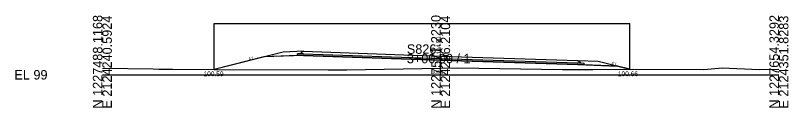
# Model space of a CAD drawing. Extents: x 2118382 to 2118616, y 1213030 to 1222057.
# Drawn here: x 2118381.9 to 2118610.4, y 1213530.1 to 1213557.3 of the extents above; entities that cross this region are included whole.
import ezdxf

# ---------------------------------------------------------------- set-up
doc = ezdxf.new("R2010")
doc.units = 0
for name, color, linetype in [('XS_CELL', 7, 'Continuous'), ('XS_M_DITCH', 7, 'Continuous'), ('XS_M_SHAPES_EARTHWORK', 7, 'Continuous'), ('XS_P_FINISHED_GRADE', 7, 'Continuous'), ('XS_P_FINISHED_GRADE_ELEV_TX', 7, 'Continuous'), ('XS_P_SUBGRADE_GRANULAR', 7, 'Continuous'), ('XS_P_SUBGRADE_PAVEMENT', 7, 'Continuous'), ('XS_P_TX_DCH', 7, 'Continuous'), ('XS_P_TX_FS_BS', 7, 'Continuous'), ('XS_X_GROUND', 7, 'Continuous'), ('XS_X_GROUND_TX', 7, 'Continuous')]:
    doc.layers.add(name, color=color, linetype=linetype)

msp = doc.modelspace()

# ---------------------------------------------------------------- linework, layer by layer
at = {"layer": 'XS_CELL'}
for p, q in [((2118507.6, 1213539.8), (2118507.6, 1213546)), ((2118407.6, 1213539.8), (2118507.6, 1213539.8)), ((2118507.6, 1213539.8), (2118607.6, 1213539.8))]:
    msp.add_line(p, q, dxfattribs=at)
at = {"layer": 'XS_M_DITCH'}
for p, q in [((2118440.64, 1213541.39), (2118440.64, 1213554.96)), ((2118440.64, 1213554.96), (2118563.5, 1213554.96)), ((2118563.5, 1213541.46), (2118563.5, 1213554.96))]:
    msp.add_line(p, q, dxfattribs=at)
at = {"layer": 'XS_M_SHAPES_EARTHWORK'}
for p, q in [((2118455.33, 1213545.07), (2118440.64, 1213541.39)), ((2118507.56, 1213544.09), (2118467.08, 1213545.54)), ((2118548.16, 1213542.83), (2118507.56, 1213544.09)), ((2118550.01, 1213542.75), (2118548.16, 1213542.83)), ((2118559.92, 1213542.36), (2118550.01, 1213542.75)), ((2118550.01, 1213542.75), (2118550.01, 1213542.75)), ((2118440.64, 1213541.39), (2118441.67, 1213541.39)), ((2118441.67, 1213541.39), (2118474.37, 1213541.22)), ((2118474.37, 1213541.22), (2118479.89, 1213541.24)), ((2118479.89, 1213541.24), (2118507.6, 1213541.77)), ((2118507.6, 1213541.77), (2118512.72, 1213541.87)), ((2118512.72, 1213541.87), (2118543.67, 1213541.39)), ((2118543.67, 1213541.39), (2118552.55, 1213541.39)), ((2118552.55, 1213541.39), (2118563.5, 1213541.46)), ((2118563.5, 1213541.46), (2118559.92, 1213542.36))]:
    msp.add_line(p, q, dxfattribs=at)
for points in [[(2118467.08, 1213545.54), (2118465.24, 1213545.46), (2118455.33, 1213545.07)], [(2118550.01, 1213542.75), (2118550.01, 1213542.75)]]:
    msp.add_lwpolyline(points, dxfattribs=at)
at = {"layer": 'XS_P_FINISHED_GRADE'}
for p, q in [((2118461.08, 1213546.5), (2118440.64, 1213541.39)), ((2118467.08, 1213546.74), (2118461.08, 1213546.5)), ((2118467.08, 1213546.74), (2118507.6, 1213545.3)), ((2118507.6, 1213545.3), (2118548.16, 1213544.04)), ((2118548.16, 1213544.04), (2118554.16, 1213543.8)), ((2118554.16, 1213543.8), (2118563.5, 1213541.46))]:
    msp.add_line(p, q, dxfattribs=at)
at = {"layer": 'XS_P_SUBGRADE_GRANULAR'}
for p, q in [((2118467.08, 1213545.54), (2118455.33, 1213545.07)), ((2118466.24, 1213546), (2118465.24, 1213545.96)), ((2118465.24, 1213545.46), (2118465.24, 1213545.96)), ((2118467.08, 1213545.54), (2118507.56, 1213544.09)), ((2118507.56, 1213544.09), (2118548.16, 1213542.83)), ((2118548.16, 1213542.83), (2118559.92, 1213542.36)), ((2118549.01, 1213543.29), (2118550.01, 1213543.25)), ((2118550.01, 1213542.75), (2118550.01, 1213543.25))]:
    msp.add_line(p, q, dxfattribs=at)
at = {"layer": 'XS_P_SUBGRADE_PAVEMENT'}
for p, q in [((2118466.39, 1213546.26), (2118466.24, 1213546)), ((2118467.08, 1213546.04), (2118466.24, 1213546)), ((2118467.08, 1213546.74), (2118466.39, 1213546.26)), ((2118467.08, 1213546.04), (2118507.58, 1213544.59)), ((2118507.58, 1213544.59), (2118548.16, 1213543.33)), ((2118548.16, 1213544.04), (2118548.86, 1213543.55)), ((2118548.16, 1213543.33), (2118549.01, 1213543.29)), ((2118548.86, 1213543.55), (2118549.01, 1213543.29))]:
    msp.add_line(p, q, dxfattribs=at)
at = {"layer": 'XS_X_GROUND'}
for p, q in [((2118407.6, 1213541.76), (2118422.59, 1213541.56)), ((2118422.59, 1213541.56), (2118424.3, 1213541.42)), ((2118424.3, 1213541.42), (2118428.37, 1213541.43)), ((2118428.37, 1213541.43), (2118441.67, 1213541.39)), ((2118441.67, 1213541.39), (2118474.37, 1213541.22)), ((2118474.37, 1213541.22), (2118479.89, 1213541.24)), ((2118479.89, 1213541.24), (2118507.6, 1213541.77)), ((2118507.6, 1213541.77), (2118512.72, 1213541.87)), ((2118512.72, 1213541.87), (2118543.67, 1213541.39)), ((2118543.67, 1213541.39), (2118552.55, 1213541.39)), ((2118552.55, 1213541.39), (2118564.69, 1213541.47)), ((2118564.69, 1213541.47), (2118585.36, 1213541.37)), ((2118585.36, 1213541.37), (2118590.78, 1213541.82)), ((2118590.78, 1213541.82), (2118601.73, 1213541.33)), ((2118601.73, 1213541.33), (2118607.6, 1213541.43))]:
    msp.add_line(p, q, dxfattribs=at)

# ---------------------------------------------------------------- texts
at = {"layer": 'XS_CELL'}
for s, p in [('N 1227488.1168', (2118407.6, 1213529.8)), ('E 2124240.5924', (2118410.4, 1213529.8)), ('N 1227571.2230', (2118507.6, 1213529.8)), ('E 2124296.2104', (2118510.4, 1213529.8)), ('N 1227654.3292', (2118607.6, 1213529.8)), ('E 2124351.8283', (2118610.4, 1213529.8))]:
    msp.add_text(s, height=2.8, rotation=90, dxfattribs=at).set_placement(p)
for s, p in [('S826', (2118497.6, 1213546)), ('3+00.00 / 1', (2118497.6, 1213543.2)), ('EL 99', (2118381.6, 1213538.4))]:
    msp.add_text(s, height=2.8, dxfattribs=at).set_placement(p)
at = {"layer": 'XS_P_FINISHED_GRADE_ELEV_TX'}
msp.add_text(' 104.50', height=1.25, rotation=90, dxfattribs=at).set_placement((2118507.6, 1213545.34))
at = {"layer": 'XS_P_TX_DCH'}
for s, p in [('100.59', (2118437.51, 1213539.39)), ('100.66', (2118560.01, 1213539.39))]:
    msp.add_text(s, height=1.4, dxfattribs=at).set_placement(p)
at = {"layer": 'XS_P_TX_FS_BS'}
for rotation, p in [(14.0362, (2118450.94, 1213544.11)), (14.0362, (2118450.94, 1213544.11)), (345.9638, (2118558.06, 1213542.96))]:
    msp.add_text('4:1', height=0.8, rotation=rotation, dxfattribs=at).set_placement(p)
at = {"layer": 'XS_X_GROUND_TX'}
msp.add_text('100.97', height=1, dxfattribs=at).set_placement((2118504.95, 1213540.04))

doc.saveas('drawing.dxf')
